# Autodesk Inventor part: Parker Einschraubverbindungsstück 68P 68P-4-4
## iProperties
Created: 2006-08
Part Number: Parker Einschraubverbindungsstück 68P 68P-4-4
Material: Messing (gelb, weich)
Description: Einschraubverbindungsstück
Document SubType Name: Modeling
Standard: Parker
Designer: Haugg
Manufacturer: Parker
Language: de-DE
Size Designation: 68P-4-4
Categories: <MemberInstance Version="R10.0.0"><Categories><Category DisplayName="Rohre und Leitungen" InternalName="4347fa0f-2144-441d-94cd-e3e15c92b736" Mnemonic="TUBEANDP
NAME: PIPING: Parker Male Connector 68P
DATA: <meta><inlinegroups number="1" deflen="2.54"></inlinegroups><connections number="2"></connections><angles><a>3.14159265358979</a></angles></meta>
Author: Haugg
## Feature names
1. Extrusion4
2. Extrusion1
3. Revolution1
4. Extrusion2
5. Extrusion3
6. Chamfer1
7. Chamfer2
8. Extrusion5
9. Revolution4
10. Extrusion6
11. Extrusion7
12. Revolution5
13. Chamfer3
14. Hole3
15. Hole4
